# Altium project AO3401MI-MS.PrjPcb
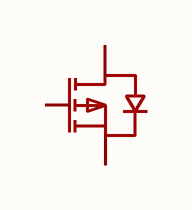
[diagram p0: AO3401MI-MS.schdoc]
1 sheet, 1 parts. Net scope: global (net labels, ports and power ports of the same name join across sheets).

## Sheet AO3401MI-MS.schdoc
size 127 x 101 mm

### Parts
Q?  ao3401mi-ms  [SOT-23-3_L2.9-W1.6-P1.90-LS2.8-BR]  (value not drawn)

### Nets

Not connected (* = marked no-connect by the designer): Q? 1(G) 2(S) 3(D)

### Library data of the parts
Q? = ao3401mi-ms: 数量:1个P沟道;漏源电压(Vdss):30V;连续漏极电流(Id):4.2A;导通电阻(RDS(on)):50mΩ@10V;耗散功率(Pd):350mW;阈值电压(Vgs(th)):900mV;; Manufacturer: MSKSEMI(美森科); AddInBom: yes; ModelId: 89cb27a44ab2466697082bb9fd73a7d0; ModelName: SOT-23-3L_L2.9-W1.6-H1.1-LS2.8-P0.95; ModelTransform: 114.173,110.236,0,90,0,0,0,0,0; Number: 1个P沟道; Drain to Source Voltage: 30V; Current - Continuous Drain(Id): 4.2A; Pd - Power Dissipation: 350mW; Gate Threshold Voltage (Vgs(th)): 900mV; Input Capacitance(Ciss): 954pF; Reverse Transfer Capacitance (Crss@Vds): 77pF; Output Capacitance(Coss): 115pF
